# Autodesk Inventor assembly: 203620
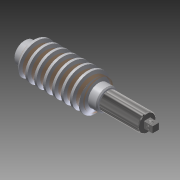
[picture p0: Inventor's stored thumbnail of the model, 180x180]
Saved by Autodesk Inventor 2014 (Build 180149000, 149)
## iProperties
Created: 2008-01
Part Number: 203620
Document SubType Name: Assembly
Designer: jjohnson
Mass: 13.5013 g
Surface Area: 38.9292 cm^2
Volume: 5.08523 cm^3
Density: 2.655 g/cm^3
Author: jjohnson
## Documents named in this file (3)
- C:\Users\iTools\Desktop\tutorial files\Automotive\2000\203620.iam
- C:\Users\iTools\Desktop\tutorial files\Automotive\2000\200910.ipt
- C:\Users\iTools\Desktop\tutorial files\Automotive\2000\200614.ipt
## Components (2 placed, 2 different names)
1. 200614:1 — Insert:1
2. Worm:1 — Insert:1
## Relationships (1: Insert 1)
- Insert:1: 200614:1 ↔ Worm:1
